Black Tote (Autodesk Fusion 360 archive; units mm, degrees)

design "Black Tote" references "Battery", "circuit breaker", "84T Spur Gear (20DP, 1/2  Hex Bore)", "Base Plate, Aluminum", "Churro for Kitbot, 17.8 In Long", "Robot Signal Light (RSL) (Allen Bradley)", "GearPulley Cluster - 3DP", "2026 Kitbot - Molded GF Nylon Clamping Collar", "Medium 1/2  Hex Flap Wheel Dark Grey", "20A Circuit Breaker", "Side Plate, Aluminum", "8mm Push on Retaining Ring", "CIM Motor", "40A Circuit Breaker", "8mm to 1/2  Hex Adapter", "Thin Hood Rail", "Flywheel, 1/2  Bore", "24t 9mm Wide Plastic Pulley (HTD 5mm, 1/2  Hex Bore)", "Spark Max Motor Controller", "10t Steel Spur Gear (20 DP, 12t Center Distance, 8mm Key Bore)", "2026 Kitbot Hex Shafts - 22  Length, 5140 Steel", "Stealth Wheel, 4 , 1/2  Hex Bore, 40 Durometer", "Transition Pulley", "2026 Kitbot Hex Bearings", "30A Circuit Breaker", "2in Compliant Wheel", "Guide Plate, Aluminum"
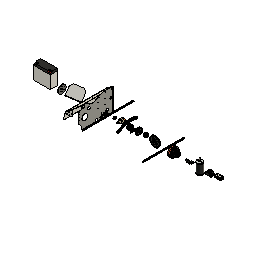
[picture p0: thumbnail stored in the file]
component_insert "Component Insert1"
component_insert "Component Insert3"
component_insert "Component Insert4"
component_insert "Component Insert5"
component_insert "Component Insert9"
component_insert "Component Insert19"
component_insert "Component Insert22"
component_insert "Component Insert23"
component_insert "Component Insert24"
component_insert "Component Insert25"
component_insert "Component Insert26"
component_insert "Component Insert27"
component_insert "Component Insert28"
component_insert "Component Insert29"
component_insert "Component Insert30"
component_insert "Component Insert31"
component_insert "Component Insert32"
component_insert "Component Insert33"
component_insert "Component Insert34"
component_insert "Component Insert35"
component_insert "Component Insert36"
component_insert "Component Insert37"
component_insert "Component Insert38"
component_insert "Component Insert39"
component_insert "Component Insert40"
component_insert "Component Insert41"
component_insert "Component Insert42"
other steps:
component_insert "Component Insert21"

design "GearPulley Cluster - 3DP"
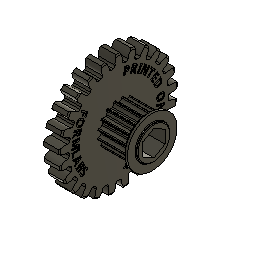
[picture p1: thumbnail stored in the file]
description: KB-26010: Launcher GearPulley
part number: KB-26010: Launcher GearPulley
base_feature "Base Feature"

design "8mm to 1/2  Hex Adapter"
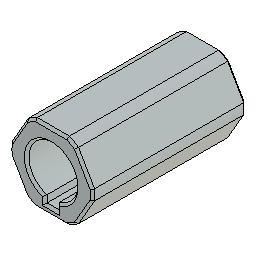
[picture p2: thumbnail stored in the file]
description: 8mm to 1/2" Hex Adapter (TTB-0044)
part number: 8mm to 1/2" Hex Adapter (TTB-0044)
base_feature "Base Feature"

design "CIM Motor"
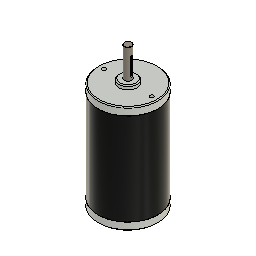
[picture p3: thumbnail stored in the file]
base_feature "Base Feature"
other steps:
create_component "CreateComponent1"

design "Transition Pulley"
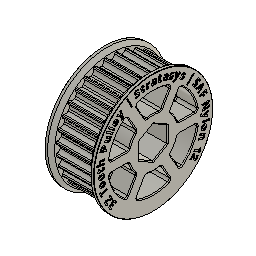
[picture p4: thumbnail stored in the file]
description: KB-26016: Transition Pulley
part number: KB-26016: Transition Pulley
base_feature "Base Feature"

design "Medium 1/2  Hex Flap Wheel Dark Grey"
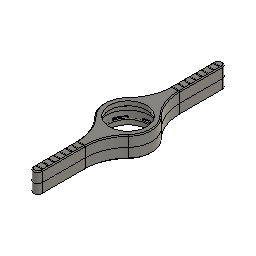
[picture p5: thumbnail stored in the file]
description: Flap
part number: Flap
base_feature "Base Feature"

design "circuit breaker"
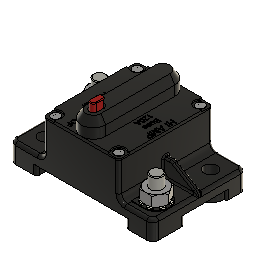
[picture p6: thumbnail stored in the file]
base_feature "Base Feature1"
base_feature "Base Feature1"
base_feature "Base Feature1"
base_feature "Base Feature1"
base_feature "Base Feature1"
base_feature "Base Feature1"
base_feature "Base Feature1"
as_built_joint "As-built1"
joint "Assemble1" alignAngle 0 alignOffsetX 0 alignOffsetY 0 alignOffsetZ 0
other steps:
create_component "CreateComponent1"
create_component "CreateComponent2"
create_component "CreateComponent3"
create_component "CreateComponent4"
create_component "CreateComponent5"
create_component "CreateComponent6"
create_component "CreateComponent7"
joint_origin "JointOrigin1"
joint_origin "JointOrigin1"

design "Battery"
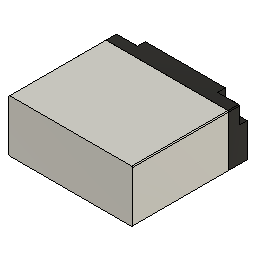
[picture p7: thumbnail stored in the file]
description: Robot Battery
part number: Robot Battery
base_feature "Base Feature"

design "Base Plate, Aluminum"
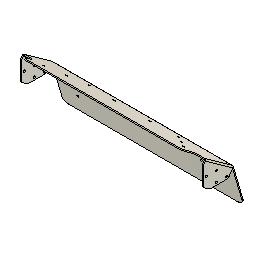
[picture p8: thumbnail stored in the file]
description: KB-26003: Intake Baseplate
part number: KB-26003: Intake Baseplate
base_feature "Base Feature"

design "2026 Kitbot - Molded GF Nylon Clamping Collar"
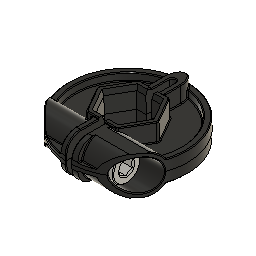
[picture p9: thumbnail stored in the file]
description: 91290A228_Alloy Steel Socket Head Screw
part number: 91290A228_Alloy Steel Socket Head Screw
description: 94459A774_Heat-Set Inserts for Plastic
part number: 94459A774_Heat-Set Inserts for Plastic
description: Shaft Collar
part number: Shaft Collar
description: Collar Prototypes <3>
part number: Collar Prototypes <3>
base_feature "Base Feature1"
base_feature "Base Feature1"
base_feature "Base Feature1"
position "Position1"
as_built_joint "As-built1"
joint "Assemble1" alignAngle -90 alignOffsetX 0 alignOffsetY 0 alignOffsetZ 0
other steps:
joint_origin "JointOrigin1"
joint_origin "JointOrigin1"

design "Robot Signal Light (RSL) (Allen Bradley)"
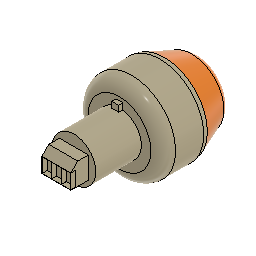
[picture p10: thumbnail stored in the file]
description: Robot Signal Light (RSL) (Allen Bradley)
part number: Robot Signal Light (RSL) (Allen Bradley)
base_feature "Base Feature"

design "40A Circuit Breaker"
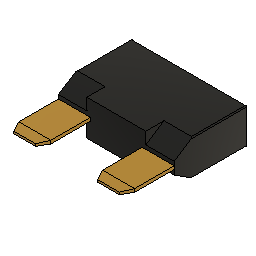
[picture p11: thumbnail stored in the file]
base_feature "Base Feature"

design "Thin Hood Rail"
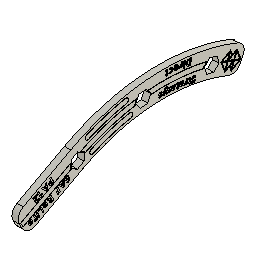
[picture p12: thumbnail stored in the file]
description: KB-26008: Hood
part number: KB-26008: Hood
base_feature "Base Feature"

design "2026 Kitbot Hex Bearings"
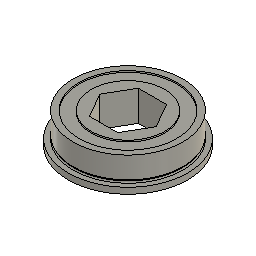
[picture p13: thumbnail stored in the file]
description: 1/2" Hex x 1-1/8" OD (Flanged)
part number: 1/2" Hex x 1-1/8" OD (Flanged)
base_feature "Base Feature"

design "Churro for Kitbot, 17.8 In Long"
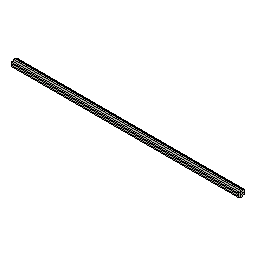
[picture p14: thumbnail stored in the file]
description: KB-26007: Brace Shaft
part number: KB-26007: Brace Shaft
base_feature "Base Feature"
move "Move1"

design "8mm Push on Retaining Ring"
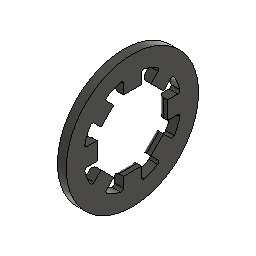
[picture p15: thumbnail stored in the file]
description: CIM Shaft Clip
part number: CIM Shaft Clip
base_feature "Base Feature"

design "Guide Plate, Aluminum"
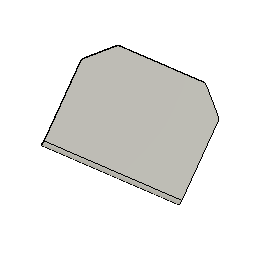
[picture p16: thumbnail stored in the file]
description: KB-26013: Intake Guide
part number: KB-26013: Intake Guide
base_feature "Base Feature"

design "2026 Kitbot Hex Shafts - 22  Length, 5140 Steel"
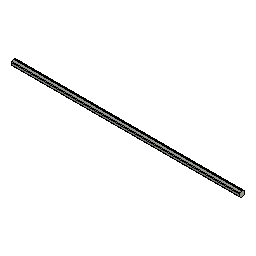
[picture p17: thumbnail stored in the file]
description: KB-26002: Roller Shaft
part number: KB-26002: Roller Shaft
base_feature "Base Feature"

design "30A Circuit Breaker"
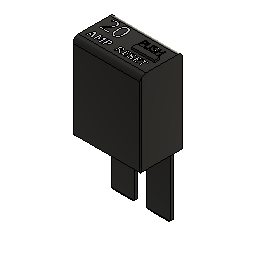
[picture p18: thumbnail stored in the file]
base_feature "Base Feature"

design "2in Compliant Wheel"
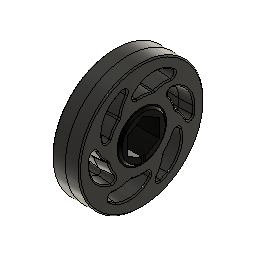
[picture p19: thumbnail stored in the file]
base_feature "Base Feature"

design "24t 9mm Wide Plastic Pulley (HTD 5mm, 1/2  Hex Bore)"
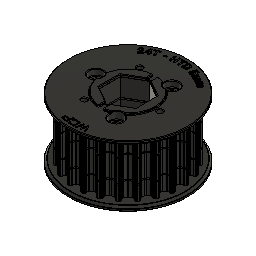
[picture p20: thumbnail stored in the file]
description: WCP-1444 Rev1
part number: WCP-1444 Rev1
base_feature "Base Feature1"
base_feature "Base Feature1"
base_feature "Base Feature1"
position "Position2"
position "Position3"
position "Position4"
as_built_joint "As-built1"
joint "Assemble1" alignAngle 0 alignOffsetX 0 alignOffsetY 0 alignOffsetZ 0
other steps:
create_component "CreateComponent1"
create_component "CreateComponent2"
create_component "CreateComponent3"
joint_origin "JointOrigin1"
joint_origin "JointOrigin1"

design "20A Circuit Breaker"
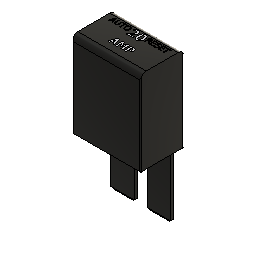
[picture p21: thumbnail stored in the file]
base_feature "Base Feature"

design "10t Steel Spur Gear (20 DP, 12t Center Distance, 8mm Key Bore)"
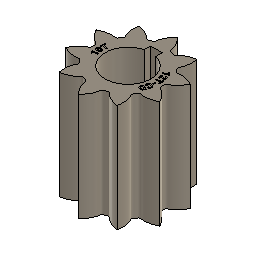
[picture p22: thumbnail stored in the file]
description: 10t Steel Spur Gear (20 DP, 12t Center Distance, 8mm Key Bore) (WCP-0899)
part number: 10t Steel Spur Gear (20 DP, 12t Center Distance, 8mm Key Bore) (WCP-0899)
base_feature "Base Feature"

design "84T Spur Gear (20DP, 1/2  Hex Bore)"
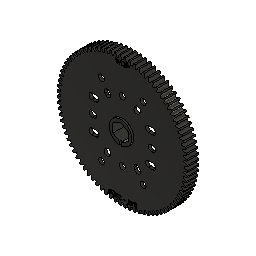
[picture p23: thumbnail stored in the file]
description: WCP-1439 Rev2
part number: WCP-1439 Rev2
base_feature "Base Feature"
